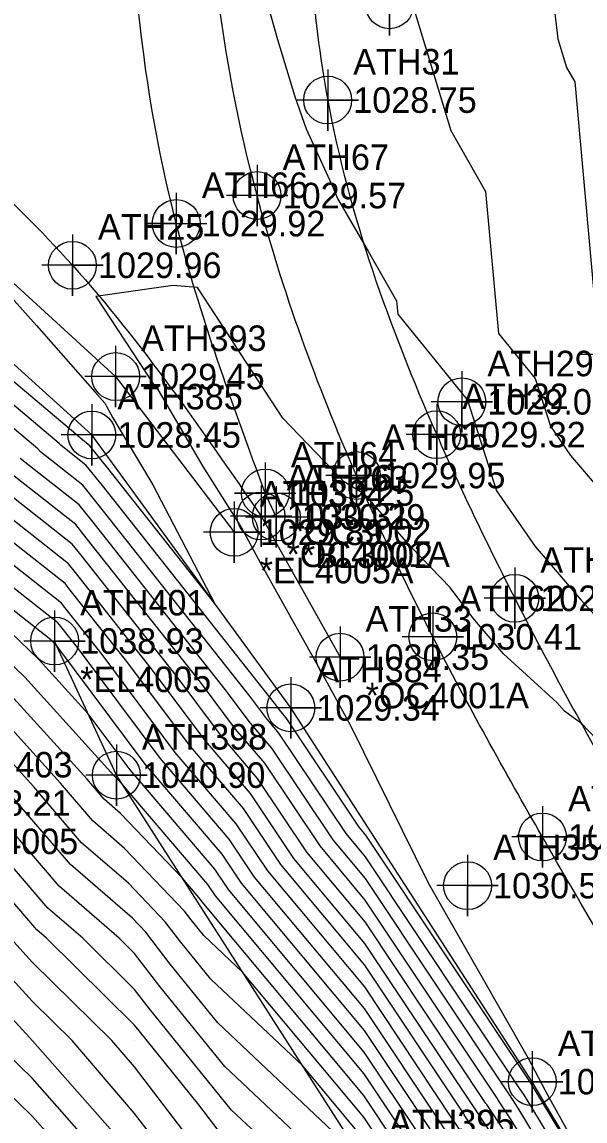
# Model space of a CAD drawing. Extents: x 1213164 to 1213550, y 766120 to 766870.
# Drawn here: x 1213299 to 1213354.1, y 766292.1 to 766399.6 of the extents above; entities that cross this region are included whole.
import ezdxf

# ---------------------------------------------------------------- set-up
doc = ezdxf.new("R2010")
doc.units = 0
for name, color, linetype in [('Default', 7, 'Continuous'), ('Exist DTM Breakline', 7, 'Continuous'), ('Exist DTM Breakline Cogo Comment', 7, 'Continuous'), ('Exist DTM Breakline Cogo Elevation', 7, 'Continuous'), ('Exist DTM Breakline Cogo Number', 7, 'Continuous'), ('Exist DTM Breakline Cogo Point CELL', 7, 'Continuous'), ('Exist DTM Crownline', 7, 'Continuous'), ('Exist DTM Crownline Cogo Elevation', 7, 'Continuous'), ('Exist DTM Crownline Cogo Number', 7, 'Continuous'), ('Exist DTM Crownline Cogo Point CELL', 7, 'Continuous'), ('Exist DTM QL2 LIDAR Elevation Point', 7, 'Continuous'), ('Exist DTM Regular Point CELL', 7, 'Continuous'), ('Exist DTM Regular Point Cogo Comment', 7, 'Continuous'), ('Exist DTM Regular Point Cogo Elevation', 7, 'Continuous'), ('Exist DTM Regular Point Cogo Number', 7, 'Continuous'), ('Exist Roads EOP', 7, 'Continuous'), ('Exist Roads EOP Cogo Point CELL', 7, 'Continuous'), ('Exist Roads EOT', 7, 'Continuous'), ('Exist Roads EOT Cogo Comment', 7, 'Continuous'), ('Exist Roads EOT Cogo Elevation', 7, 'Continuous'), ('Exist Roads EOT Cogo Number', 7, 'Continuous'), ('Exist Roads EOT Cogo Point CELL', 7, 'Continuous')]:
    doc.layers.add(name, color=color, linetype=linetype)

msp = doc.modelspace()

# ---------------------------------------------------------------- linework, layer by layer
at = {"layer": 'Default'}
for points in [[(1213350.53, 766405.47), (1213351.41, 766397.98), (1213352.26, 766395.19), (1213353.06, 766393.79), (1213355.46, 766367.31), (1213355.81, 766366.88), (1213355.95, 766366.43), (1213356.14, 766366.16), (1213359.09, 766362.71), (1213368.17, 766350.82), (1213372.16, 766342.87), (1213379.17, 766331.01), (1213381.68, 766326.4), (1213391.02, 766310.47), (1213396.59, 766300.3), (1213401.19, 766291.42)], [(1213323.04, 766401.29), (1213323.99, 766397.94), (1213325.67, 766392.35), (1213326.8, 766389.18), (1213329.42, 766383.4), (1213329.86, 766382.37), (1213332.88, 766377.14), (1213335.62, 766372.35), (1213335.74, 766371.05), (1213342.56, 766362.65), (1213345.41, 766353.78), (1213349.18, 766348.33), (1213353.68, 766343.08), (1213359.26, 766336.95), (1213363.62, 766332.42), (1213369.17, 766324.84), (1213373.89, 766319.9), (1213377.31, 766316.31), (1213389.25, 766299.05), (1213392.73, 766294.19), (1213400.2, 766281.6)], [(1213337.36, 766400.83), (1213340.93, 766389.02), (1213344.34, 766383.07), (1213345.6, 766369.18), (1213349.19, 766364.77), (1213350.68, 766360.11), (1213352.66, 766357.24), (1213365.05, 766342.75), (1213366.94, 766340.68), (1213368.42, 766339.15), (1213378.42, 766325.5), (1213379.05, 766324.85), (1213379.5, 766324.37), (1213383.69, 766318.32), (1213393.03, 766302.36), (1213394.64, 766299.43), (1213395.96, 766296.87), (1213404.69, 766277.75)], [(1213272.27, 766399.73), (1213280.23, 766392.59), (1213283.94, 766389.17), (1213286.04, 766386.64), (1213286.45, 766385.98), (1213289.98, 766381.54), (1213300.38, 766369.94), (1213306.11, 766363.46), (1213307.08, 766362.36), (1213307.88, 766360.91), (1213311.79, 766354.35), (1213317.8, 766342.79), (1213307.37, 766355.98), (1213305.62, 766358.19), (1213304.73, 766358.89), (1213304.68, 766358.95), (1213282.81, 766377.37), (1213280.62, 766379.22), (1213253.86, 766381.44), (1213252.1, 766381.97)], [(1213358.83, 766325.69), (1213353.75, 766330.97), (1213352.06, 766332.23), (1213351.32, 766333.08), (1213346.1, 766337.83), (1213343.11, 766341.34), (1213340.86, 766344.31), (1213337.11, 766348.19), (1213332.53, 766353.43), (1213330.49, 766354.65), (1213330.17, 766354.98), (1213324.5, 766360.89), (1213320.36, 766367.22), (1213319.53, 766368.48), (1213316.14, 766373.67), (1213313.73, 766373.86), (1213306.21, 766372.78), (1213311.89, 766364.13), (1213312.16, 766363.84), (1213316.67, 766356.16), (1213320.45, 766350.15), (1213322.3, 766346.7), (1213328.43, 766335.78), (1213331.13, 766330.81), (1213338.73, 766315.43), (1213348.51, 766298.27), (1213350.13, 766295.17), (1213350.21, 766295.04), (1213360.65, 766276.21), (1213348.89, 766295.63), (1213348.83, 766295.74), (1213348.73, 766295.89), (1213332.62, 766320.1), (1213331.98, 766320.86), (1213324.82, 766331.57), (1213324.3, 766332.17), (1213323.69, 766332.99), (1213306.84, 766354.28), (1213305.27, 766356.26), (1213302.76, 766358.24), (1213302.6, 766358.41), (1213282.15, 766375.64)], [(1213362.76, 766270.48), (1213348.21, 766294.51), (1213347.73, 766295.24), (1213347.64, 766295.38), (1213332.6, 766317.97), (1213330.7, 766320.25), (1213324.12, 766330.08), (1213322.83, 766331.6), (1213321.28, 766333.67), (1213306.32, 766352.58), (1213304.93, 766354.34), (1213300.78, 766357.59), (1213300.52, 766357.87), (1213281.49, 766373.9)], [(1213427.02, 766169.17), (1213422.12, 766170.87), (1213409.81, 766193.38), (1213408.21, 766196.08), (1213407.9, 766196.6), (1213393.25, 766219.97), (1213391.95, 766221.91), (1213385.49, 766232.22), (1213385.15, 766232.72), (1213370.45, 766254.79), (1213368.43, 766257.88), (1213362.35, 766267), (1213359.46, 766271.43), (1213346.86, 766292.25), (1213345.54, 766294.24), (1213345.47, 766294.36), (1213332.57, 766313.73), (1213328.14, 766319.03), (1213322.73, 766327.12), (1213319.88, 766330.46), (1213316.46, 766335.04), (1213305.27, 766349.17), (1213304.23, 766350.49), (1213296.83, 766356.3)], [(1213361.11, 766270.95), (1213347.54, 766293.38), (1213346.64, 766294.74), (1213346.56, 766294.87), (1213332.59, 766315.85), (1213329.42, 766319.64), (1213323.42, 766328.6), (1213321.35, 766331.03), (1213318.87, 766334.35), (1213305.8, 766350.87), (1213304.58, 766352.41), (1213298.81, 766356.95)], [(1213425.78, 766168.77), (1213421.23, 766170.35), (1213409.8, 766191.25), (1213407.24, 766195.57), (1213406.74, 766196.41), (1213392.93, 766218.45), (1213390.76, 766221.69), (1213384.66, 766231.42), (1213384.09, 766232.28), (1213370.2, 766253.11), (1213367.37, 766257.44), (1213361.68, 766265.98), (1213357.81, 766271.9), (1213346.18, 766291.12), (1213344.45, 766293.74), (1213344.38, 766293.85), (1213332.56, 766311.61), (1213326.86, 766318.42), (1213322.03, 766325.64), (1213318.4, 766329.89), (1213314.05, 766335.72), (1213304.75, 766347.47), (1213303.88, 766348.56), (1213294.86, 766355.65)], [(1213423.3, 766167.96), (1213419.45, 766169.3), (1213409.77, 766186.99), (1213405.3, 766194.56), (1213404.43, 766196.02), (1213392.28, 766215.39), (1213388.37, 766221.24), (1213382.99, 766229.82), (1213381.95, 766231.39), (1213369.71, 766249.75), (1213365.24, 766256.58), (1213360.35, 766263.93), (1213354.51, 766272.85), (1213344.82, 766288.87), (1213342.26, 766292.74), (1213342.2, 766292.83), (1213332.53, 766307.36), (1213324.3, 766317.21), (1213320.64, 766322.68), (1213315.45, 766328.75), (1213309.22, 766337.08), (1213303.7, 766344.06), (1213303.19, 766344.71), (1213290.91, 766354.36)], [(1213424.54, 766168.36), (1213420.34, 766169.83), (1213409.79, 766189.12), (1213406.27, 766195.06), (1213405.59, 766196.21), (1213392.6, 766216.92), (1213389.56, 766221.46), (1213383.82, 766230.62), (1213383.02, 766231.83), (1213369.96, 766251.43), (1213366.3, 766257.01), (1213361.02, 766264.95), (1213356.16, 766272.38), (1213345.5, 766290), (1213343.35, 766293.24), (1213343.29, 766293.34), (1213332.54, 766309.48), (1213325.58, 766317.82), (1213321.33, 766324.16), (1213316.92, 766329.32), (1213311.63, 766336.4), (1213304.22, 766345.77), (1213303.53, 766346.64), (1213292.88, 766355.01)], [(1213420.82, 766167.16), (1213417.67, 766168.26), (1213409.75, 766182.74), (1213403.35, 766193.54), (1213402.12, 766195.63), (1213391.64, 766212.34), (1213385.98, 766220.8), (1213381.33, 766228.22), (1213379.81, 766230.49), (1213369.21, 766246.39), (1213363.12, 766255.71), (1213359.01, 766261.88), (1213351.22, 766273.8), (1213343.46, 766286.61), (1213340.07, 766291.74), (1213340.02, 766291.81), (1213332.5, 766303.12), (1213321.74, 766315.99), (1213319.25, 766319.71), (1213312.5, 766327.61), (1213304.4, 766338.44), (1213302.65, 766340.66), (1213302.49, 766340.86), (1213286.96, 766353.07)], [(1213422.06, 766167.56), (1213418.56, 766168.78), (1213409.76, 766184.86), (1213404.32, 766194.05), (1213403.27, 766195.83), (1213391.96, 766213.87), (1213387.17, 766221.02), (1213382.16, 766229.02), (1213380.88, 766230.94), (1213369.46, 766248.07), (1213364.18, 766256.14), (1213359.68, 766262.9), (1213352.86, 766273.33), (1213344.14, 766287.74), (1213341.16, 766292.24), (1213341.11, 766292.32), (1213332.51, 766305.24), (1213323.02, 766316.6), (1213319.94, 766321.2), (1213313.97, 766328.18), (1213306.81, 766337.76), (1213303.18, 766342.36), (1213302.84, 766342.79), (1213288.93, 766353.71)], [(1213419.58, 766166.76), (1213416.78, 766167.74), (1213409.74, 766180.61), (1213402.38, 766193.03), (1213400.96, 766195.44), (1213391.31, 766210.82), (1213384.78, 766220.58), (1213380.5, 766227.42), (1213378.74, 766230.05), (1213368.97, 766244.72), (1213362.06, 766255.27), (1213358.34, 766260.85), (1213349.57, 766274.28), (1213342.78, 766285.49), (1213338.97, 766291.24), (1213338.94, 766291.3), (1213332.48, 766300.99), (1213320.46, 766315.38), (1213318.55, 766318.23), (1213311.02, 766327.04), (1213302.39, 766338.6), (1213302.07, 766338.95), (1213301.81, 766339.2), (1213284.98, 766352.42)], [(1213336.76, 766290.28), (1213332.45, 766296.75), (1213317.9, 766314.16), (1213317.16, 766315.27), (1213308.78, 766325.08), (1213308.25, 766325.63), (1213308.11, 766325.75), (1213307.96, 766325.92), (1213299.26, 766335.54), (1213291.94, 766342.56)], [(1213418.34, 766166.36), (1213415.89, 766167.21), (1213409.72, 766178.48), (1213401.41, 766192.53), (1213399.8, 766195.24), (1213390.99, 766209.29), (1213383.59, 766220.36), (1213379.66, 766226.62), (1213377.67, 766229.6), (1213368.72, 766243.04), (1213360.99, 766254.84), (1213357.67, 766259.83), (1213347.92, 766274.75), (1213342.1, 766284.36), (1213337.88, 766290.74), (1213337.85, 766290.79), (1213332.47, 766298.87), (1213319.18, 766314.77), (1213317.85, 766316.75), (1213309.55, 766326.47), (1213305.45, 766331.96), (1213300.66, 766337.25), (1213296.87, 766340.88)], [(1213415.86, 766165.56), (1213414.11, 766166.17), (1213409.7, 766174.22), (1213399.47, 766191.51), (1213397.49, 766194.86), (1213390.35, 766206.24), (1213381.2, 766219.91), (1213378, 766225.02), (1213375.53, 766228.71), (1213368.22, 766239.68), (1213358.87, 766253.97), (1213356.33, 766257.78), (1213344.62, 766275.7), (1213340.74, 766282.1), (1213335.69, 766289.74), (1213335.67, 766289.77), (1213332.44, 766294.62), (1213316.62, 766313.55), (1213316.46, 766313.79), (1213314.67, 766315.89), (1213308.63, 766322.21), (1213307.01, 766323.62), (1213305.35, 766325.55), (1213297.86, 766333.83)], [(1213334.58, 766289.26), (1213332.42, 766292.5), (1213320.56, 766306.7), (1213316.77, 766310.28), (1213315.53, 766311.8), (1213314.89, 766312.64), (1213309.02, 766318.79), (1213305.91, 766321.49), (1213302.74, 766325.18), (1213296.46, 766332.13)], [(1213332.41, 766290.38), (1213326.45, 766297.51), (1213317.45, 766306.01), (1213314.51, 766309.63), (1213312.99, 766311.61), (1213309.4, 766315.38), (1213304.81, 766319.35), (1213300.14, 766324.8), (1213295.05, 766330.42)], [(1213327.91, 766288.87), (1213318.81, 766297.46), (1213312.47, 766305.28), (1213310, 766308.5), (1213308.48, 766310), (1213302.62, 766315.09), (1213294.92, 766324.06)], [(1213412.14, 766164.36), (1213411.43, 766164.6), (1213409.66, 766167.84), (1213396.55, 766189.99), (1213394.01, 766194.27), (1213389.38, 766201.66), (1213377.62, 766219.25), (1213375.5, 766222.62), (1213372.32, 766227.38), (1213367.48, 766234.65), (1213355.68, 766252.67), (1213354.33, 766254.71), (1213339.67, 766277.13), (1213338.7, 766278.72), (1213332.4, 766288.24), (1213332.4, 766288.24), (1213332.39, 766288.26), (1213332.33, 766288.33), (1213318.13, 766301.73), (1213313.49, 766307.46), (1213311.09, 766310.59), (1213309.78, 766311.96), (1213303.72, 766317.22), (1213297.53, 766324.43)], [(1213319.12, 766290), (1213316.29, 766293.71), (1213310.44, 766300.93), (1213310, 766301.5), (1213301.37, 766310), (1213300.42, 766310.82), (1213289.7, 766323.31)], [(1213323.38, 766289.52), (1213319.49, 766293.19), (1213311.46, 766303.11), (1213310, 766305), (1213304.93, 766310), (1213301.52, 766312.95), (1213292.31, 766323.68)], [(1213308.8, 766290), (1213300, 766299.98), (1213299.97, 766300), (1213299.71, 766300.29), (1213290.8, 766310)], [(1213312.19, 766290), (1213310, 766292.87), (1213303.87, 766300), (1213300, 766303.81), (1213294.32, 766310)], [(1213315.66, 766290), (1213310, 766297.41), (1213307.77, 766300), (1213300, 766307.64), (1213297.84, 766310)], [(1213302.28, 766290), (1213300, 766292.58), (1213292.36, 766300)], [(1213305.54, 766290), (1213300, 766296.28), (1213296.17, 766300)]]:
    msp.add_lwpolyline(points, dxfattribs=at)
at = {"layer": 'Exist DTM Breakline'}
for points in [[(1213422.78, 766171.25), (1213409.83, 766196.93), (1213386.66, 766233.35), (1213364.33, 766270.03), (1213348.91, 766295.97), (1213348.91, 766295.97), (1213325.28, 766332.54), (1213305.81, 766359.24), (1213281.25, 766381.47), (1213256.99, 766395.59), (1213227.81, 766408.56), (1213197.43, 766416.07)], [(1213246.75, 766405.84), (1213265.53, 766398.39), (1213284.18, 766386.84), (1213308.14, 766364.95), (1213319.74, 766349.72)], [(1213409.64, 766163.55), (1213387.59, 766193.2), (1213366.02, 766224.76), (1213332.39, 766288.23), (1213308.21, 766325.96), (1213302.17, 766339.08)]]:
    msp.add_lwpolyline(points, dxfattribs=at)
at = {"layer": 'Exist DTM Breakline Cogo Point CELL'}
for points in [[(1213356.52, 766370.11), (1213356.52, 766364.11), (1213356.52, 766367.11), (1213359.52, 766367.11), (1213353.52, 766367.11)], [(1213308.14, 766367.95), (1213308.14, 766361.95), (1213308.14, 766364.95), (1213311.14, 766364.95), (1213305.14, 766364.95)], [(1213305.81, 766362.24), (1213305.81, 766356.24), (1213305.81, 766359.24), (1213308.81, 766359.24), (1213302.81, 766359.24)], [(1213319.74, 766352.72), (1213319.74, 766346.72), (1213319.74, 766349.72), (1213322.74, 766349.72), (1213316.74, 766349.72)], [(1213302.17, 766342.08), (1213302.17, 766336.08), (1213302.17, 766339.08), (1213305.17, 766339.08), (1213299.17, 766339.08)], [(1213325.28, 766335.54), (1213325.28, 766329.54), (1213325.28, 766332.54), (1213328.28, 766332.54), (1213322.28, 766332.54)], [(1213308.21, 766328.96), (1213308.21, 766322.96), (1213308.21, 766325.96), (1213311.21, 766325.96), (1213305.21, 766325.96)], [(1213348.91, 766298.97), (1213348.91, 766292.97), (1213348.91, 766295.97), (1213351.91, 766295.97), (1213345.91, 766295.97)]]:
    msp.add_lwpolyline(points, dxfattribs=at)
for centre in [(1213308.14, 766364.95), (1213305.81, 766359.24), (1213319.74, 766349.72), (1213302.17, 766339.08), (1213325.28, 766332.54), (1213308.21, 766325.96), (1213348.91, 766295.97)]:
    msp.add_circle(centre, 2.34, dxfattribs=at)
at = {"layer": 'Exist DTM Crownline'}
msp.add_spline([(1213364.82, 766294.53), (1213349.91, 766319.91), (1213339.18, 766339.49), (1213331.7, 766355.27), (1213321.98, 766382.66), (1213317.52, 766424.05), (1213319.57, 766440.21), (1213325.28, 766470.16)], degree=3, dxfattribs=at)
at = {"layer": 'Exist DTM Crownline Cogo Point CELL'}
for points in [[(1213321.98, 766385.66), (1213321.98, 766379.66), (1213321.98, 766382.66), (1213324.98, 766382.66), (1213318.98, 766382.66)], [(1213331.7, 766358.27), (1213331.7, 766352.27), (1213331.7, 766355.27), (1213334.7, 766355.27), (1213328.7, 766355.27)], [(1213339.18, 766342.49), (1213339.18, 766336.49), (1213339.18, 766339.49), (1213342.18, 766339.49), (1213336.18, 766339.49)], [(1213349.91, 766322.91), (1213349.91, 766316.91), (1213349.91, 766319.91), (1213352.91, 766319.91), (1213346.91, 766319.91)]]:
    msp.add_lwpolyline(points, dxfattribs=at)
for centre in [(1213321.98, 766382.66), (1213331.7, 766355.27), (1213339.18, 766339.49), (1213349.91, 766319.91)]:
    msp.add_circle(centre, 2.34, dxfattribs=at)
at = {"layer": 'Exist DTM QL2 LIDAR Elevation Point'}
for p, q in [((1213300, 766310), (1213300, 766310)), ((1213310, 766310), (1213310, 766310)), ((1213300, 766300), (1213300, 766300)), ((1213310, 766300), (1213310, 766300))]:
    msp.add_line(p, q, dxfattribs=at)
at = {"layer": 'Exist DTM Regular Point CELL'}
for points in [[(1213334.94, 766404.32), (1213334.94, 766398.32), (1213334.94, 766401.32), (1213337.94, 766401.32), (1213331.94, 766401.32)], [(1213342.02, 766365.48), (1213342.02, 766359.48), (1213342.02, 766362.48), (1213345.02, 766362.48), (1213339.02, 766362.48)]]:
    msp.add_lwpolyline(points, dxfattribs=at)
for centre in [(1213334.94, 766401.32), (1213342.02, 766362.48)]:
    msp.add_circle(centre, 2.34, dxfattribs=at)
at = {"layer": 'Exist Roads EOP'}
msp.add_line((1213322.37, 766351.31), (1213330.1, 766337.5), dxfattribs=at)
for points in [[(1213331.54, 766460.38), (1213328.2, 766439.13), (1213326.88, 766418.06), (1213328.89, 766392), (1213339.56, 766359.27), (1213347.2, 766343.26), (1213357.64, 766324.02), (1213372.58, 766298.93)], [(1213169.01, 766424.2), (1213197.36, 766422.68), (1213222.73, 766418.67), (1213259.83, 766408.16), (1213283.39, 766394.33), (1213303.91, 766375.84), (1213322.37, 766351.31)]]:
    msp.add_spline(points, degree=3, dxfattribs=at)
at = {"layer": 'Exist Roads EOP Cogo Point CELL'}
for points in [[(1213328.89, 766395), (1213328.89, 766389), (1213328.89, 766392), (1213331.89, 766392), (1213325.89, 766392)], [(1213303.91, 766378.84), (1213303.91, 766372.84), (1213303.91, 766375.84), (1213306.91, 766375.84), (1213300.91, 766375.84)], [(1213339.56, 766362.27), (1213339.56, 766356.27), (1213339.56, 766359.27), (1213342.56, 766359.27), (1213336.56, 766359.27)], [(1213322.37, 766354.31), (1213322.37, 766348.31), (1213322.37, 766351.31), (1213325.37, 766351.31), (1213319.37, 766351.31)], [(1213347.2, 766346.26), (1213347.2, 766340.26), (1213347.2, 766343.26), (1213350.2, 766343.26), (1213344.2, 766343.26)], [(1213330.1, 766340.5), (1213330.1, 766334.5), (1213330.1, 766337.5), (1213333.1, 766337.5), (1213327.1, 766337.5)], [(1213342.58, 766318.15), (1213342.58, 766312.15), (1213342.58, 766315.15), (1213345.58, 766315.15), (1213339.58, 766315.15)]]:
    msp.add_lwpolyline(points, dxfattribs=at)
for centre in [(1213328.89, 766392), (1213303.91, 766375.84), (1213339.56, 766359.27), (1213322.37, 766351.31), (1213347.2, 766343.26), (1213330.1, 766337.5), (1213342.58, 766315.15)]:
    msp.add_circle(centre, 2.34, dxfattribs=at)
at = {"layer": 'Exist Roads EOT'}
msp.add_line((1213323.86, 766351.22), (1213322.78, 766353.56), dxfattribs=at)
msp.add_spline([(1213322.78, 766353.56), (1213314.07, 766379.92), (1213309.74, 766424.63), (1213313.33, 766456.61)], degree=3, dxfattribs=at)
at = {"layer": 'Exist Roads EOT Cogo Point CELL'}
for points in [[(1213314.07, 766382.92), (1213314.07, 766376.92), (1213314.07, 766379.92), (1213311.07, 766379.92), (1213317.07, 766379.92)], [(1213322.78, 766356.56), (1213322.78, 766350.56), (1213322.78, 766353.56), (1213319.78, 766353.56), (1213325.78, 766353.56)], [(1213323.86, 766354.22), (1213323.86, 766348.22), (1213323.86, 766351.22), (1213320.86, 766351.22), (1213326.86, 766351.22)]]:
    msp.add_lwpolyline(points, dxfattribs=at)
for centre in [(1213314.07, 766379.92), (1213322.78, 766353.56), (1213323.86, 766351.22)]:
    msp.add_circle(centre, 2.34, dxfattribs=at)

# ---------------------------------------------------------------- texts
at = {"layer": 'Exist DTM Breakline Cogo Comment'}
for s, p in [('*EL4005A', (1213322.24, 766344.72)), ('*EL4005', (1213304.67, 766334.08)), ('*BL4005', (1213291.65, 766318.23))]:
    msp.add_text(s, height=2.5, dxfattribs=at).set_placement(p)
at = {"layer": 'Exist DTM Breakline Cogo Elevation'}
for s, p in [('1029.45', (1213310.64, 766363.7)), ('1028.45', (1213308.31, 766357.99)), ('1029.89', (1213322.24, 766348.47)), ('1038.93', (1213304.67, 766337.83)), ('1029.34', (1213327.78, 766331.29)), ('1040.90', (1213310.71, 766324.71)), ('1048.21', (1213291.65, 766321.98)), ('1029.84', (1213351.41, 766294.72))]:
    msp.add_text(s, height=2.5, dxfattribs=at).set_placement(p)
at = {"layer": 'Exist DTM Breakline Cogo Number'}
for s, p in [('ATH393', (1213310.64, 766367.45)), ('ATH385', (1213308.31, 766361.74)), ('ATH394', (1213322.24, 766352.22)), ('ATH401', (1213304.67, 766341.58)), ('ATH384', (1213327.78, 766335.04)), ('ATH398', (1213310.71, 766328.46)), ('ATH403', (1213291.65, 766325.73)), ('ATH383', (1213351.41, 766298.47)), ('ATH395', (1213334.89, 766290.73))]:
    msp.add_text(s, height=2.5, dxfattribs=at).set_placement(p)
at = {"layer": 'Exist DTM Crownline Cogo Elevation'}
for s, p in [('1029.57', (1213324.48, 766381.41)), ('1029.95', (1213334.2, 766354.02)), ('1030.41', (1213341.68, 766338.24)), ('1030.86', (1213352.41, 766318.66))]:
    msp.add_text(s, height=2.5, dxfattribs=at).set_placement(p)
at = {"layer": 'Exist DTM Crownline Cogo Number'}
for s, p in [('ATH67', (1213324.48, 766385.16)), ('ATH65', (1213334.2, 766357.77)), ('ATH62', (1213341.68, 766341.99)), ('ATH61', (1213352.41, 766322.41))]:
    msp.add_text(s, height=2.5, dxfattribs=at).set_placement(p)
at = {"layer": 'Exist DTM Regular Point Cogo Comment'}
for p in [(1213324.87, 766346.31), (1213332.6, 766332.5)]:
    msp.add_text('*OC4001A', height=2.5, dxfattribs=at).set_placement(p)
at = {"layer": 'Exist DTM Regular Point Cogo Elevation'}
for s, p in [('1028.75', (1213331.39, 766390.75)), ('1029.96', (1213306.41, 766374.59)), ('1029.08', (1213344.52, 766361.23)), ('1029.32', (1213342.06, 766358.02)), ('1030.31', (1213324.87, 766350.06)), ('1029.57', (1213349.7, 766342.01)), ('1030.35', (1213332.6, 766336.25)), ('1030.57', (1213345.08, 766313.9))]:
    msp.add_text(s, height=2.5, dxfattribs=at).set_placement(p)
at = {"layer": 'Exist DTM Regular Point Cogo Number'}
for s, p in [('ATH31', (1213331.39, 766394.5)), ('ATH25', (1213306.41, 766378.34)), ('ATH299', (1213344.52, 766364.98)), ('ATH32', (1213342.06, 766361.77)), ('ATH26', (1213324.87, 766353.81)), ('ATH34', (1213349.7, 766345.76)), ('ATH33', (1213332.6, 766340)), ('ATH35', (1213345.08, 766317.65))]:
    msp.add_text(s, height=2.5, dxfattribs=at).set_placement(p)
at = {"layer": 'Exist Roads EOT Cogo Comment'}
for s, p in [('*OC3002', (1213325.28, 766348.56)), ('*BL3002', (1213326.36, 766346.22))]:
    msp.add_text(s, height=2.5, dxfattribs=at).set_placement(p)
at = {"layer": 'Exist Roads EOT Cogo Elevation'}
for s, p in [('1029.92', (1213316.57, 766378.67)), ('1030.25', (1213325.28, 766352.31)), ('1030.29', (1213326.36, 766349.97))]:
    msp.add_text(s, height=2.5, dxfattribs=at).set_placement(p)
at = {"layer": 'Exist Roads EOT Cogo Number'}
for s, p in [('ATH66', (1213316.57, 766382.42)), ('ATH64', (1213325.28, 766356.06)), ('ATH63', (1213326.36, 766353.72))]:
    msp.add_text(s, height=2.5, dxfattribs=at).set_placement(p)

doc.saveas('drawing.dxf')
